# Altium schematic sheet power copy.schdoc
size 260 x 185 mm
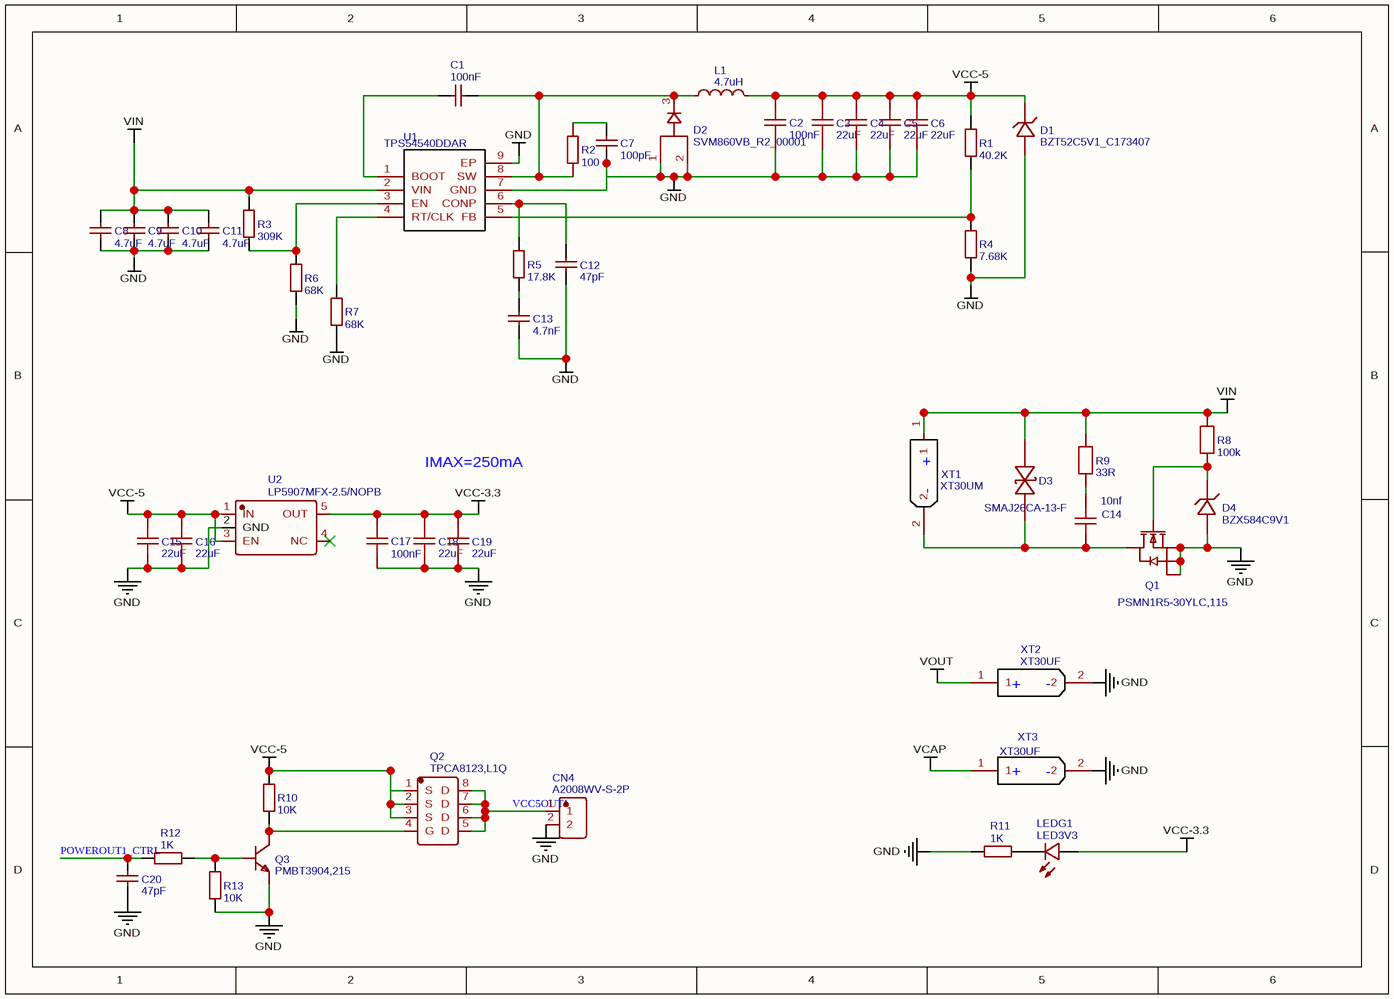
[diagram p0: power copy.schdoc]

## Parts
C1  100nF  [C0603]
C2  100nF  [C0603]
C3  22uF  [C0603]
C4  22uF  [C0603]
C5  22uF  [C0603]
C6  22uF  [C0603]
C7  100pF  [C0603]
C8  4.7uF  [C0805]
C9  4.7uF  [C0805]
C10  4.7uF  [C0805]
C11  4.7uF  [C0805]
C12  47pF  [C0402]
C13  4.7nF  [C0402]
C14  10nf  [C0603]
C15  22uF  [C0603]
C16  22uF  [C0603]
C17  100nF  [C0402]
C18  22uF  [C0603]
C19  22uF  [C0603]
C20  47pF  [C0402]
CN4  A2008WV-S-2P  [CONN-SMD_A2008WV-S-2P]
D1  BZT52C5V1_C173407  [SOD-123_L2.7-W1.6-LS3.7-RD]
D2  SVM860VB_R2_00001  [TO-277B_3P-L6.1-W4.3-LS7.0-BR]
D3  SMAJ26CA-13-F  [SMA_L4.4-W2.6-LS5.0-BI]
D4  BZX584C9V1  [SOD-523F_L1.7-W0.9-LS1.7-RD]
L1  4.7uH  [IND-SMD_L6.0-W6.0]
LEDG1  LED3V3  [LED-0603]
Q1  PSMN1R5-30YLC,115  [SOT-669_L4.9-W4.0-P1.27-LS6.0-BR]
Q2  TPCA8123,L1Q  [POWERVDFN-8_L6.0-W5.0-P1.27-BL]
Q3  PMBT3904,215  [SOT-23_L2.9-W1.3-P0.95-LS2.4-BR]
R1  40.2K  [R0603]
R2  100  [R0402]
R3  309K  [R0603]
R4  7.68K  [R0402]
R5  17.8K  [R0603]
R6  68K  [R0603]
R7  68K  [R0603]
R8  100k  [R0603]
R9  33R  [R0603]
R10  10K  [R0402]
R11  1K  [R0603]
R12  1K  [R0402]
R13  10K  [R0402]
U1  TPS54540DDAR  [SOIC-8_L4.9-W3.9-P1.27-LS6.0-BL-EP]
U2  LP5907MFX-2.5/NOPB  [SOT-23-5_L3.0-W1.7-P0.95-LS2.8-BL]
XT1  XT30UM  [CONN-TH_XT30UPB-F]
XT2  XT30UF  [CONN-TH_XT30UPB-F]
XT3  XT30UF  [CONN-TH_XT30UPB-F]

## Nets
GND: C2.1 C3.1 C4.1 C5.1 C6.1 C7.2 C8.1 C9.1 C10.1 C11.1 C12.1 C13.1 C15.1 C16.1 C17.1 C18.1 C19.1 C20.1 CN4.2 D1.2(A) D2.1 D2.2 D4.2(A) Q1.1(S) Q1.2(S) Q1.3(S) Q3.2 R4.1 R6.1 R7.1 R11.1 R13.1 U1.7(GND) U1.9(EP) U2.2(GND) XT2.2 XT3.2
VCAP: XT3.1
VCC-3.3: C17.2 C18.2 C19.2 LEDG1.1(A) U2.5(OUT)
VCC-5: C2.2 C3.2 C4.2 C5.2 C6.2 C15.2 C16.2 D1.1(C) L1.2 Q2.1(S) Q2.2(S) Q2.3(S) R1.2 R10.2 U2.1(IN) U2.3(EN)
VIN: C8.2 C9.2 C10.2 C11.2 D3.2 R3.2 R8.2 R9.2 U1.2(VIN) XT1.1
VOUT: XT2.1
POWEROUT1_CTRL: C20.2 R12.1
VCC5OUT1: CN4.1 Q2.5(D) Q2.6(D) Q2.7(D) Q2.8(D)
NetC1_1: C1.1 U1.1(BOOT)
NetC1_2: C1.2 D2.3 L1.1 R2.1 U1.8(SW)
NetC7_1: C7.1 R2.2
NetC12_2: C12.2 R5.2 U1.6(CONP)
NetC13_2: C13.2 R5.1
NetC14_1: C14.1 D3.1 Q1.5(D) XT1.2
NetC14_2: C14.2 R9.1
NetD4_1: D4.1(K) Q1.4(G) R8.1
NetLEDG1_2: LEDG1.2(C) R11.2
NetQ2_4: Q2.4(G) Q3.3 R10.1
NetQ3_1: Q3.1 R12.2 R13.2
NetR1_1: R1.1 R4.2 U1.5(FB)
NetR3_1: R3.1 R6.2 U1.3(EN)
NetR7_2: R7.2 U1.4(RT/CLK)

Not connected (* = marked no-connect by the designer): U2 4(NC)*

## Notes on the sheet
- IMAX=250mA

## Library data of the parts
C1 = 100nF: BOM_Manufacturer Part: CL05B104KO5NNNC; BOM_Manufacturer: SAMSUNG; nameAlias: Capacitance
C2 = 100nF: BOM_Manufacturer: YAGEO; BOM_Manufacturer Part: AC0603KRX7R0BB104; nameAlias: Capacitance; Contributor: LCSC
C3-C6 C15 C16 C18 C19 = 22uF: BOM_Manufacturer: SAMSUNG; BOM_Manufacturer Part: CL10A226MQ8NRNC; nameAlias: Capacitance; SMT Type: Basic
C7 = 100pF: BOM_Manufacturer Part: CGA3E2C0G1H101JT0Y0N; BOM_Manufacturer: TDK; nameAlias: Capacitance
C8-C11 = 4.7uF: BOM_Manufacturer: SAMSUNG; BOM_Manufacturer Part: CL21A475KBQNNNE; nameAlias: Capacitance
C12 C20 = 47pF: BOM_Manufacturer: FH; BOM_Manufacturer Part: 0402CG470J500NT; nameAlias: Capacitance; SMT Type: Basic
C13 = 4.7nF: BOM_Manufacturer: FH; BOM_Manufacturer Part: 0402B472K500NT; nameAlias: Capacitance; SMT Type: Basic
C14 = 10nf: nameAlias: Value(F)
C17 = 100nF: BOM_Manufacturer: MuRata; BOM_Manufacturer Part: GRM188R71H104KA93D; nameAlias: Capacitance
CN4 = A2008WV-S-2P: BOM_Manufacturer: Changjiang Connectors; Contributor: LCSC
D1 = BZT52C5V1_C173407: BOM_Manufacturer: (MDD) Jiangsu Yutai Elec; Contributor: LCSC; SMT Type: Extend
D2 = SVM860VB_R2_00001: BOM_Manufacturer: PANJIT International; Contributor: LCSC
D3 = SMAJ26CA-13-F: BOM_Manufacturer: DIODES; Contributor: LCSC; SMT Type: Extend
D4 = BZX584C9V1: SMT Type: Extend
L1 = 4.7uH: BOM_Manufacturer: ShunXiang Connaught Elec; BOM_Manufacturer Part: SMNR6028-4R7MT; nameAlias: Inductance; Contributor: LCSC
LEDG1 = LED3V3: BOM_Manufacturer: EVERLIGHT; BOM_Manufacturer Part: 19-217/GHC-YR1S2/3T
Q1 = PSMN1R5-30YLC,115: BOM_Manufacturer: Nexperia; Contributor: LCSC
Q2 = TPCA8123,L1Q: BOM_Manufacturer: TOSHIBA; Contributor: LCSC; SMT Type: Extend
Q3 = PMBT3904,215: BOM_Manufacturer: Nexperia; SMT Type: Extend
R1 = 40.2K: BOM_Manufacturer: UniOhm; BOM_Manufacturer Part: 0603WAF4022T5E; nameAlias: Resistance (Ohms); SMT Type: Basic
R2 = 100: BOM_Manufacturer: YAGEO; BOM_Manufacturer Part: AC0402FR-07100RL; nameAlias: Resistance (Ohms); Contributor: LCSC
R3 = 309K: BOM_Manufacturer: UniOhm; BOM_Manufacturer Part: 0603WAF3093T5E; nameAlias: Resistance (Ohms); SMT Type: Extend
R4 = 7.68K: BOM_Manufacturer: UniOhm; BOM_Manufacturer Part: 0402WGF7681TCE; nameAlias: Resistance (Ohms); SMT Type: Extend
R5 = 17.8K: BOM_Manufacturer: UniOhm; BOM_Manufacturer Part: 0603WAF1782T5E; nameAlias: Resistance (Ohms); SMT Type: Extend
R6 R7 = 68K: BOM_Manufacturer: UniOhm; BOM_Manufacturer Part: 0603WAF6802T5E; nameAlias: Resistance (Ohms); SMT Type: Basic
R8 = 100k: nameAlias: Value(Ω)
R9 = 33R: nameAlias: Value(Ω)
R10 R13 = 10K: BOM_Manufacturer: UniOhm; BOM_Manufacturer Part: 0402WGF1002TCE; nameAlias: Resistance (Ohms); SMT Type: Basic
R11 R12 = 1K: BOM_Manufacturer: UniOhm; BOM_Manufacturer Part: 0402WGF1001TCE; nameAlias: Resistance (Ohms); SMT Type: Basic
U1 = TPS54540DDAR: BOM_Manufacturer: TI; SMT Type: Extend
U2 = LP5907MFX-2.5/NOPB: BOM_Manufacturer: TI; Contributor: LCSC; SMT Type: Extend
XT1 = XT30UM: BOM_Manufacturer Part: XT60; Contributor: 4bucks; Package Display: No
XT2 XT3 = XT30UF: BOM_Manufacturer Part: XT60; Contributor: 4bucks; Package Display: No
